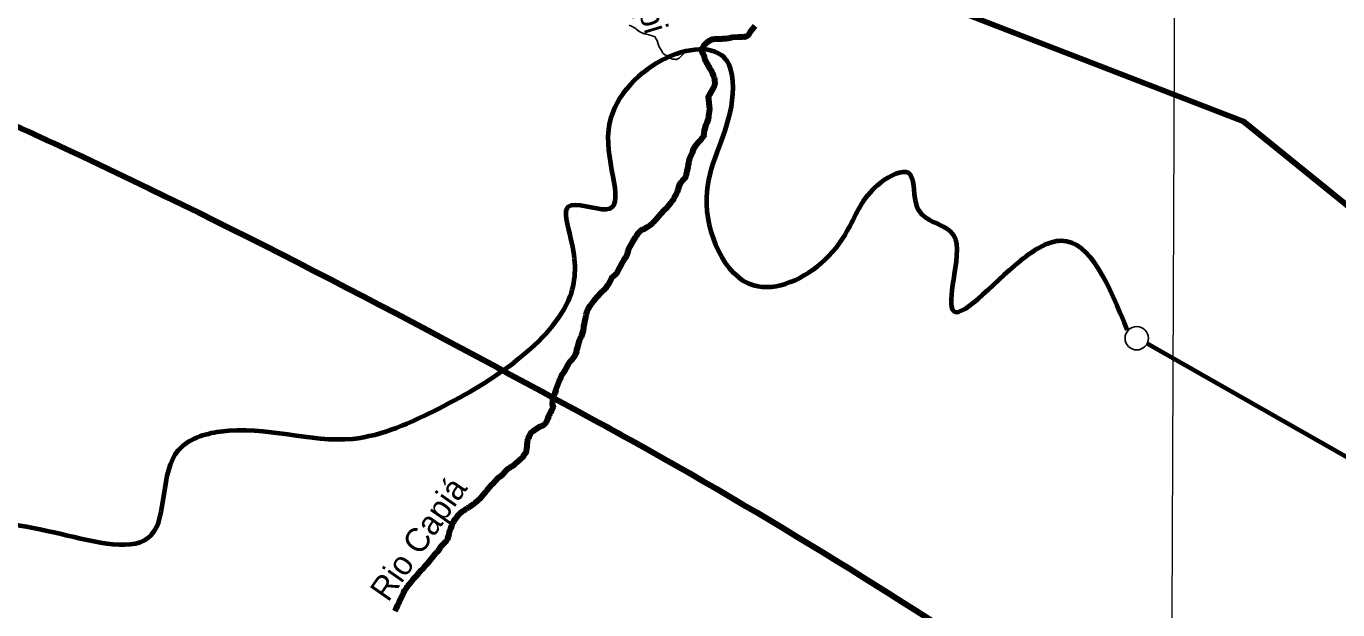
# Model space of a CAD drawing. Extents: x 553962 to 842807, y 8883888 to 9032388.
# Drawn here: x 640695 to 668185, y 8961392 to 8973626 of the extents above; entities that cross this region are included whole.
import ezdxf
from ezdxf.enums import TextEntityAlignment as Align

# ---------------------------------------------------------------- set-up
doc = ezdxf.new("R2010")
doc.units = 0
doc.header["$LTSCALE"] = 200
for name, color, linetype, lineweight in [('1', 7, 'Continuous', 13), ('24', 7, 'Continuous', 25), ('27', 7, 'Continuous', 25), ('51', 7, 'Continuous', 70), ('9', 7, 'Continuous', 90)]:
    doc.layers.add(name, color=color, linetype=linetype, lineweight=lineweight)
doc.layers.add('49', color=7, linetype='Continuous')

msp = doc.modelspace()

# ---------------------------------------------------------------- linework, layer by layer
at = {"layer": '1'}
msp.add_lwpolyline([(664968.2, 9023436.8), (664657.1, 8949509), (664397.1, 8890880.2)], dxfattribs=at)
at = {"layer": '24'}
for p, q in [((655116.6, 8973422.7), (655117, 8973424.3)), ((654851.3, 8973132), (654755.7, 8973142.7))]:
    msp.add_line(p, q, dxfattribs=at)
msp.add_lwpolyline([(654755.7, 8973142.7), (654720.6, 8973132.1), (654647.5, 8973144.9), (654604.9, 8973142), (654598.8, 8973140.5), (654534.6, 8973104.9), (654437.3, 8973012.6), (654419.5, 8972998.8), (654403.8, 8972979.2), (654381.6, 8972957.8), (654363, 8972946.1), (654335.2, 8972931.4), (654326.4, 8972929.3), (654308.8, 8972928.4), (654287.9, 8972933.5), (654250.2, 8972934.8), (654229.3, 8972940.7), (654192.4, 8972956.2), (654152.5, 8972986.8), (654147.8, 8972992.5), (654142.1, 8972995.3), (654139, 8973001.3), (654076, 8973035.9), (654041.5, 8973060), (654027.3, 8973074.1), (654028.3, 8973079.5), (653955, 8973206), (653948.8, 8973231.1), (653931.5, 8973279.1), (653918, 8973324.5), (653906.3, 8973348.1), (653892.5, 8973371.7), (653880.9, 8973398.6), (653873.4, 8973402.2), (653869.2, 8973406.6), (653838.8, 8973418.7), (653790.9, 8973428.7), (653697.5, 8973459.4), (653649.6, 8973468.4), (653604, 8973484.9), (653582.4, 8973495.6), (653556.1, 8973510.9), (653509.5, 8973541.4), (653482.9, 8973561.9), (653470.5, 8973577.6), (653442.6, 8973592.3), (653395.4, 8973620.1), (653335.2, 8973650.9)], dxfattribs=at)
at = {"layer": '24', "lineweight": 53}
for points in [[(655968.2, 8973630.5), (655940.3, 8973590.2), (655926.4, 8973572.3), (655907.2, 8973551.6), (655857.4, 8973488), (655825.2, 8973435), (655819.5, 8973432.4), (655817.1, 8973428.1), (655813, 8973426.4), (655807.3, 8973421.2), (655797.6, 8973417.6), (655794, 8973413), (655766.8, 8973403.9), (655745.4, 8973399.7), (655722.2, 8973400.4), (655702.5, 8973398.4), (655680.3, 8973394.3), (655616.9, 8973396.2), (655501.2, 8973386.6), (655443.3, 8973378), (655404.8, 8973367.5), (655366.2, 8973362.1), (655326.8, 8973361.9), (655289.1, 8973358.7), (655269, 8973355.7), (655249.7, 8973356.6), (655212, 8973355.5), (655191.9, 8973353.5), (655154.1, 8973354.5), (655137.5, 8973353.6), (655077.8, 8973346), (655060.3, 8973342.2), (655039.3, 8973335.4), (655029.9, 8973329.2), (655023.6, 8973328.5), (655016.9, 8973321.8), (654963.5, 8973284.3), (654916.4, 8973246.2), (654900.8, 8973228.3), (654881.6, 8973201), (654851.3, 8973132), (654852.3, 8973113.8), (654858.7, 8973088.2), (654878.1, 8973056.9), (654895, 8973014.3), (654909.2, 8972953.2), (654915.3, 8972934.7), (654923.6, 8972916.2), (654947.3, 8972875.3), (654982.1, 8972819.3), (654996.2, 8972794.1), (655005.3, 8972774), (655014.6, 8972757.2), (655044.4, 8972710.5), (655053.7, 8972692), (655056.5, 8972676.5), (655080.1, 8972632.6), (655093.2, 8972594.1), (655109.8, 8972556.3), (655111.9, 8972544), (655121.8, 8972516.9), (655124, 8972498.5), (655124.2, 8972478.4), (655127.3, 8972439.8), (655123.7, 8972391.1), (655118.2, 8972380.4), (655102.9, 8972341.9), (654992.2, 8972144.1), (655019.8, 8971884.2), (654998.6, 8971745.3), (654995, 8971695.3), (654989.7, 8971685.4), (654957.7, 8971597.4), (654937.6, 8971556.5), (654925.2, 8971519.5), (654918.6, 8971481), (654907, 8971442.4), (654896.1, 8971382.9), (654895.8, 8971344.4), (654892, 8971324.4), (654883.1, 8971306.7), (654872.7, 8971291.8), (654840.1, 8971251.1), (654818.4, 8971232.1), (654818.4, 8971232.1), (654777.1, 8971189.8), (654713.1, 8971114), (654675.8, 8971041.8), (654665.8, 8971017.4), (654650.1, 8970966.2), (654641.7, 8970946), (654616.5, 8970899.6)], [(654616.5, 8970899.6), (654597.8, 8970850.8), (654585.3, 8970804.5), (654581.2, 8970781.8), (654578.8, 8970758.3), (654572.6, 8970734.7), (654560.7, 8970664), (654554.4, 8970640.4), (654550, 8970616.9), (654542.2, 8970591.6), (654533, 8970547), (654526.8, 8970523.4), (654524.2, 8970501.2), (654508.2, 8970458.4), (654499, 8970437.8), (654493.5, 8970429), (654477.7, 8970417.1), (654443, 8970382.2), (654421.1, 8970358.3), (654389.5, 8970306.2), (654379.5, 8970284), (654365, 8970242.8), (654351.1, 8970197.8), (654345.4, 8970173.5), (654336.8, 8970149.9), (654324.7, 8970123.6), (654288, 8970056.4), (654272.8, 8970031.9), (654254.6, 8969979.6), (654230.2, 8969960.2), (654218.1, 8969945.2), (654200.3, 8969917.9), (654115.1, 8969812.6), (654066, 8969768.5), (653998.5, 8969693.6), (653949.1, 8969634.7), (653875.5, 8969551.6), (653848.1, 8969526.1), (653826.1, 8969509.2), (653807.7, 8969485.9), (653788.8, 8969465.8), (653781.7, 8969461.6), (653774.9, 8969453.3), (653733.8, 8969425.9), (653708.2, 8969413.9), (653656.8, 8969380.9), (653631.1, 8969367), (653605.4, 8969356.1), (653579.7, 8969340.1), (653534.3, 8969303.2), (653514.9, 8969279.7), (653477.3, 8969225.2), (653456.6, 8969199.3), (653405, 8969106.7), (653344.1, 8969008.1), (653319.5, 8968956.7), (653307.6, 8968905.3), (653300.6, 8968881.3), (653288.5, 8968853.8), (653281.5, 8968827.4), (653256.7, 8968776), (653222.5, 8968726.1), (653207.9, 8968699.7), (653188.9, 8968672.3), (653150.5, 8968597.6), (653133.3, 8968569.4), (653084.6, 8968470), (653068.7, 8968444.2), (653061.9, 8968437.6), (653060, 8968431.6), (653055, 8968429.5), (653045.5, 8968418.5), (652999.2, 8968380.5), (652979.1, 8968362.1), (652966, 8968345), (652949.9, 8968318.3), (652925.3, 8968271.2), (652905.8, 8968224.1), (652891.4, 8968201.3), (652870.7, 8968180.1), (652835.3, 8968129.2), (652814.8, 8968105.2), (652767.5, 8968061.3), (652745.1, 8968043.8), (652652.7, 8967947.3), (652575.9, 8967853), (652512.8, 8967770.6), (652464.1, 8967693.3), (652444.9, 8967645.2), (652429.5, 8967596.4), (652427.1, 8967572.9), (652423, 8967550.1), (652401.8, 8967461), (652386.5, 8967384.3), (652386.5, 8967384.3), (652384.2, 8967360.8), (652378.1, 8967337.2), (652377.6, 8967311.9), (652365.4, 8967244.7), (652334.5, 8967142.4), (652334.2, 8967141.5)], [(652334.2, 8967141.5), (652324.2, 8967104.9), (652322.5, 8967102.9), (652317.1, 8967102.6), (652315.6, 8967101.2), (652313.2, 8967092.4), (652305.8, 8967079.3), (652284.1, 8967031.6), (652276.2, 8967009.5), (652248.5, 8966903.2), (652229.6, 8966839.8), (652226.8, 8966816.7), (652221.7, 8966796.1), (652207.8, 8966753.2), (652174.8, 8966688.9), (652160.4, 8966666.8), (652125.1, 8966623.9), (652084.5, 8966580), (652063.4, 8966553.7), (652047.7, 8966528.9), (652014.7, 8966461.6), (651981.7, 8966407.3), (651960.2, 8966375.4), (651944.1, 8966347.6), (651912.1, 8966302.5), (651898.2, 8966276.2), (651897.4, 8966264.9), (651885.1, 8966236.2), (651874.7, 8966216.8), (651867.7, 8966193.9), (651851, 8966156.5), (651798.1, 8966019.3), (651792.6, 8965994.6), (651772.9, 8965932.8), (651759.8, 8965907.9), (651741.4, 8965863.8), (651729.4, 8965826.5), (651723.3, 8965779.3), (651720.3, 8965699.1), (651722.8, 8965675), (651743.5, 8965648.6), (651743.4, 8965644.6), (651698.9, 8965564), (651693.6, 8965544.1), (651688.2, 8965540.4), (651686.5, 8965534.9), (651674.3, 8965514.2), (651664.3, 8965494.4), (651655.9, 8965471.5), (651645.4, 8965450), (651637.1, 8965429.3), (651623.4, 8965385), (651601.4, 8965342.9), (651591.7, 8965321.5), (651577.2, 8965299.5), (651559.6, 8965280.8), (651533.4, 8965257.4), (651515.3, 8965247.1), (651499.6, 8965244.2), (651496.3, 8965241.1), (651479.6, 8965235.3), (651466.6, 8965226.9), (651443.2, 8965217.1), (651307.6, 8965130.1), (651287.6, 8965112.6), (651272.7, 8965096.7), (651258.7, 8965075.1), (651231.1, 8965023.9), (651213.3, 8964982.5), (651203.9, 8964956.5), (651195.2, 8964907.3), (651191.2, 8964841.6), (651191, 8964817.2), (651164.9, 8964678.6), (651157.3, 8964676.2), (651155.4, 8964668.4), (651148.9, 8964664.2), (651138.2, 8964651.3), (651124.9, 8964632.4), (651105.4, 8964599.6), (651094.6, 8964583.9), (651089.5, 8964580.2), (651065.3, 8964555.2), (651012.9, 8964509), (650998.5, 8964498.8), (650986.4, 8964486.1), (650949.3, 8964456), (650900.6, 8964412.3), (650874.5, 8964393.6), (650844.8, 8964377.2), (650826.4, 8964368.8), (650809.3, 8964357.4), (650785.7, 8964337.7), (650747.8, 8964302.8), (650693.7, 8964240.3), (650662, 8964208.7), (650662, 8964208.7), (650632.1, 8964188.2), (650618, 8964175.7), (650604.2, 8964169.9), (650589.6, 8964160.3)], [(650589.6, 8964160.3), (650574.3, 8964146.5), (650530.2, 8964098.3), (650509, 8964077.9), (650473.5, 8964033), (650442.6, 8964005.1), (650368.1, 8963919.8), (650346, 8963888.5), (650332.8, 8963874.9), (650310.5, 8963845.9), (650278.5, 8963808.1), (650264.2, 8963793.4), (650207.7, 8963725.5), (650176.4, 8963697.3), (650153.9, 8963678.9), (650140.4, 8963665.7), (650124.7, 8963653.2), (650103.3, 8963631.9), (650086.5, 8963618), (650072.4, 8963608.2), (650060.6, 8963597.7), (650046.6, 8963590.1), (650000.4, 8963555.6), (649955.2, 8963530.6), (649939, 8963520), (649922.4, 8963511.9), (649893.1, 8963492), (649865.1, 8963469.6), (649835.2, 8963451.3), (649777.6, 8963401.4), (649742.6, 8963367.3), (649718.9, 8963335.7), (649704, 8963312.6), (649674.6, 8963276.8), (649661.2, 8963257.8), (649648.9, 8963237.2), (649640.8, 8963219.3), (649630.7, 8963202.8), (649615, 8963169.3), (649608.8, 8963150.8), (649584.8, 8963092.3), (649563.2, 8963031.5), (649555.5, 8962980.1), (649545.2, 8962946.6), (649541.4, 8962928), (649515.6, 8962859.5), (649507.1, 8962843.2), (649499.9, 8962833.4), (649481.2, 8962814.6), (649475.3, 8962806.6), (649456.2, 8962788.3), (649449.4, 8962778.8), (649420.2, 8962753.5), (649395, 8962724.1), (649367.2, 8962685.5), (649343.5, 8962648.1), (649319.4, 8962615.6), (649289.5, 8962584.5), (649264.9, 8962562.7), (649217.7, 8962504.2), (649187.2, 8962469.5), (649162, 8962433.2), (649131.5, 8962399.3), (649105.7, 8962365.4), (649075.9, 8962335.3), (649056.5, 8962311.9), (649027.9, 8962268.9), (649013.5, 8962252.7), (648961.3, 8962205.6), (648876.1, 8962105.7), (648858.3, 8962087.9), (648839.2, 8962071.7), (648801.6, 8962026.5), (648742.1, 8961950.5), (648715.9, 8961919), (648698.4, 8961903), (648678.4, 8961875.1), (648665.1, 8961852.7), (648623.9, 8961794), (648612.1, 8961775.1), (648600.3, 8961752.7), (648585.9, 8961717.7), (648566.1, 8961679.4), (648547.4, 8961632), (648528.6, 8961598.4), (648520.4, 8961575.2), (648506.1, 8961547), (648501.5, 8961529.9), (648482.2, 8961497.1), (648474.8, 8961478.5), (648456.4, 8961445.7), (648449.2, 8961427.1), (648419.2, 8961360.9)]]:
    msp.add_lwpolyline(points, dxfattribs=at)
at = {"layer": '24'}
msp.add_spline([(665209.5, 8949437.1), (665261.8, 8949907.3), (665888.8, 8950560.5), (666750.9, 8951187.5), (667665.3, 8951814.5), (668344.5, 8952363.1), (668788.7, 8952911.7), (669180.6, 8953564.9), (669154.4, 8954270.2), (669755.3, 8954662.1), (670486.8, 8955027.9), (671218.3, 8955785.5), (671166.1, 8956360.3), (671531.8, 8956726), (671479.6, 8956987.3), (670957.1, 8957405.3), (670695.8, 8957849.4), (671139.9, 8958502.5), (671845.3, 8959207.9), (672394, 8958789.9), (673047.1, 8959234), (673465.1, 8959834.9), (673177.7, 8960461.9), (673987.6, 8960749.3), (675163.2, 8960879.9), (676103.7, 8960906.1), (677253.2, 8961428.6), (677697.4, 8961559.2), (678115.4, 8962133.9), (678611.8, 8962369.1), (678820.8, 8962919.9), (679291, 8963704.1), (679918, 8964226.8), (679944.1, 8964697.3), (679709, 8965272.3), (679291, 8966004.2), (678115.4, 8966945.2)], degree=3, dxfattribs=at)
at = {"layer": '27'}
msp.add_circle((663971.4, 8967084.9), 244.7, dxfattribs=at)
at = {"layer": '51'}
msp.add_line((664185.1, 8966978.4), (668643.6, 8964441.9), dxfattribs=at)
msp.add_spline([(592045.3, 8966365.8), (592105.7, 8965948), (594116, 8966514), (595498, 8965319.1), (597037.2, 8966136.7), (597979.5, 8965382), (598692.6, 8967300.2), (598221.4, 8968337.9), (598818.2, 8968400.8), (599792, 8969092.6), (600231.7, 8968589.5), (601299.7, 8967960.6), (602901.6, 8966545.5), (604566.4, 8966482.6), (604745.5, 8965696.5), (605405.1, 8964973.2), (606347.4, 8965067.5), (606598.7, 8965916.6), (607760.9, 8966168.1), (606881.4, 8967363.1), (606818.6, 8968966.8), (608671.8, 8969249.8), (610641.3, 8969878.8), (611740.7, 8970224.7), (613019.2, 8969721.5), (613813.8, 8969815.9), (614966.7, 8967143), (615657.7, 8967897.7), (616819.9, 8967551.8), (618578.9, 8965130.4), (619826, 8965948), (620642.7, 8965633.6), (621804.8, 8965948), (623218.3, 8965539.2), (624506.2, 8966105.2), (626233.7, 8967551.8), (628149.5, 8965483.5), (628181, 8964376.2), (628353.9, 8962908.5), (629301.3, 8963064.1), (629808.6, 8963286.1), (631079.5, 8963482.7), (632397.9, 8963531.7), (633735.2, 8964126.9), (635403.4, 8963798.6), (639270.5, 8963331.4), (641424.7, 8962981.9), (643321.9, 8962962.5), (643886.9, 8964740.5), (644763.1, 8965131.4), (647540.5, 8964979.2), (649340.2, 8965613.4), (651021.3, 8966658.1), (652098.8, 8967969.1), (652112.8, 8969176.8), (652061.5, 8969848.1), (652848.6, 8969790.3), (652905.5, 8971456.6), (655366.6, 8972918.5), (655467.9, 8971938.7), (654952.1, 8970029.5), (655937.5, 8968195.9), (657437.3, 8968728.9), (657964, 8969442.1), (658605, 8970350.9), (659181.8, 8970558.1), (659395.9, 8969769.5), (660070.2, 8969323), (660146.3, 8968426.2), (660105.6, 8967692), (661532.3, 8968708.4), (662385.2, 8969131.8), (663773.8, 8967258.4)], degree=3, dxfattribs=at)
at = {"layer": '9'}
for points in [[(657923.9, 8974844.3), (666205.7, 8971636.3), (671933.6, 8966993.4), (675245, 8966459.9), (693230.3, 8967549.5), (697027.9, 8970867.6)], [(655968.2, 8973630.5), (655940.3, 8973590.2), (655926.4, 8973572.3), (655907.2, 8973551.6), (655857.4, 8973488), (655825.2, 8973435), (655819.5, 8973432.4), (655817.1, 8973428.1), (655813, 8973426.4), (655807.3, 8973421.2), (655797.6, 8973417.6), (655794, 8973413), (655766.8, 8973403.9), (655745.4, 8973399.7), (655722.2, 8973400.4), (655702.5, 8973398.4), (655680.3, 8973394.3), (655616.9, 8973396.2), (655501.2, 8973386.6), (655443.3, 8973378), (655404.8, 8973367.5), (655366.2, 8973362.1), (655326.8, 8973361.9), (655289.1, 8973358.7), (655269, 8973355.7), (655249.7, 8973356.6), (655212, 8973355.5), (655191.9, 8973353.5), (655154.1, 8973354.5), (655137.5, 8973353.6), (655077.8, 8973346), (655060.3, 8973342.2), (655039.3, 8973335.4), (655029.9, 8973329.2), (655023.6, 8973328.5), (655016.9, 8973321.8), (654963.5, 8973284.3), (654916.4, 8973246.2), (654900.8, 8973228.3), (654881.6, 8973201), (654851.3, 8973132), (654852.3, 8973113.8), (654858.7, 8973088.2), (654878.1, 8973056.9), (654895, 8973014.3), (654909.2, 8972953.2), (654915.3, 8972934.7), (654923.6, 8972916.2), (654947.3, 8972875.3), (654982.1, 8972819.3), (654996.2, 8972794.1), (655005.3, 8972774), (655014.6, 8972757.2), (655044.4, 8972710.5), (655053.7, 8972692), (655056.5, 8972676.5), (655080.1, 8972632.6), (655093.2, 8972594.1), (655109.8, 8972556.3), (655111.9, 8972544), (655121.8, 8972516.9), (655124, 8972498.5), (655124.2, 8972478.4), (655127.3, 8972439.8), (655123.7, 8972391.1), (655118.2, 8972380.4), (655102.9, 8972341.9), (654992.2, 8972144.1), (655019.8, 8971884.2), (654998.6, 8971745.3), (654995, 8971695.3), (654989.7, 8971685.4), (654957.7, 8971597.4), (654937.6, 8971556.5), (654925.2, 8971519.5), (654918.6, 8971481), (654907, 8971442.4), (654896.1, 8971382.9), (654895.8, 8971344.4), (654892, 8971324.4), (654883.1, 8971306.7), (654872.7, 8971291.8), (654840.1, 8971251.1), (654818.4, 8971232.1), (654818.4, 8971232.1), (654777.1, 8971189.8), (654713.1, 8971114), (654675.8, 8971041.8), (654665.8, 8971017.4), (654650.1, 8970966.2), (654641.7, 8970946), (654616.5, 8970899.6)], [(654616.5, 8970899.6), (654597.8, 8970850.8), (654585.3, 8970804.5), (654581.2, 8970781.8), (654578.8, 8970758.3), (654572.6, 8970734.7), (654560.7, 8970664), (654554.4, 8970640.4), (654550, 8970616.9), (654542.2, 8970591.6), (654533, 8970547), (654526.8, 8970523.4), (654524.2, 8970501.2), (654508.2, 8970458.4), (654499, 8970437.8), (654493.5, 8970429), (654477.7, 8970417.1), (654443, 8970382.2), (654421.1, 8970358.3), (654389.5, 8970306.2), (654379.5, 8970284), (654365, 8970242.8), (654351.1, 8970197.8), (654345.4, 8970173.5), (654336.8, 8970149.9), (654324.7, 8970123.6), (654288, 8970056.4), (654272.8, 8970031.9), (654254.6, 8969979.6), (654230.2, 8969960.2), (654218.1, 8969945.2), (654200.3, 8969917.9), (654115.1, 8969812.6), (654066, 8969768.5), (653998.5, 8969693.6), (653949.1, 8969634.7), (653875.5, 8969551.6), (653848.1, 8969526.1), (653826.1, 8969509.2), (653807.7, 8969485.9), (653788.8, 8969465.8), (653781.7, 8969461.6), (653774.9, 8969453.3), (653733.8, 8969425.9), (653708.2, 8969413.9), (653656.8, 8969380.9), (653631.1, 8969367), (653605.4, 8969356.1), (653579.7, 8969340.1), (653534.3, 8969303.2), (653514.9, 8969279.7), (653477.3, 8969225.2), (653456.6, 8969199.3), (653405, 8969106.7), (653344.1, 8969008.1), (653319.5, 8968956.7), (653307.6, 8968905.3), (653300.6, 8968881.3), (653288.5, 8968853.8), (653281.5, 8968827.4), (653256.7, 8968776), (653222.5, 8968726.1), (653207.9, 8968699.7), (653188.9, 8968672.3), (653150.5, 8968597.6), (653133.3, 8968569.4), (653084.6, 8968470), (653068.7, 8968444.2), (653061.9, 8968437.6), (653060, 8968431.6), (653055, 8968429.5), (653045.5, 8968418.5), (652999.2, 8968380.5), (652979.1, 8968362.1), (652966, 8968345), (652949.9, 8968318.3), (652925.3, 8968271.2), (652905.8, 8968224.1), (652891.4, 8968201.3), (652870.7, 8968180.1), (652835.3, 8968129.2), (652814.8, 8968105.2), (652767.5, 8968061.3), (652745.1, 8968043.8), (652652.7, 8967947.3), (652575.9, 8967853), (652512.8, 8967770.6), (652464.1, 8967693.3), (652444.9, 8967645.2), (652429.5, 8967596.4), (652427.1, 8967572.9), (652423, 8967550.1), (652401.8, 8967461), (652386.5, 8967384.3), (652386.5, 8967384.3), (652384.2, 8967360.8), (652378.1, 8967337.2), (652377.6, 8967311.9), (652365.4, 8967244.7), (652334.5, 8967142.4), (652334.2, 8967141.5)], [(652334.2, 8967141.5), (652324.2, 8967104.9), (652322.5, 8967102.9), (652317.1, 8967102.6), (652315.6, 8967101.2), (652313.2, 8967092.4), (652305.8, 8967079.3), (652284.1, 8967031.6), (652276.2, 8967009.5), (652248.5, 8966903.2), (652229.6, 8966839.8), (652226.8, 8966816.7), (652221.7, 8966796.1), (652207.8, 8966753.2), (652174.8, 8966688.9), (652160.4, 8966666.8), (652125.1, 8966623.9), (652084.5, 8966580), (652063.4, 8966553.7), (652047.7, 8966528.9), (652014.7, 8966461.6), (651981.7, 8966407.3), (651960.2, 8966375.4), (651944.1, 8966347.6), (651912.1, 8966302.5), (651898.2, 8966276.2), (651897.4, 8966264.9), (651885.1, 8966236.2), (651874.7, 8966216.8), (651867.7, 8966193.9), (651851, 8966156.5), (651798.1, 8966019.3), (651792.6, 8965994.6), (651772.9, 8965932.8), (651759.8, 8965907.9), (651741.4, 8965863.8), (651729.4, 8965826.5), (651723.3, 8965779.3), (651720.3, 8965699.1), (651722.8, 8965675), (651743.5, 8965648.6), (651743.4, 8965644.6), (651698.9, 8965564), (651693.6, 8965544.1), (651688.2, 8965540.4), (651686.5, 8965534.9), (651674.3, 8965514.2), (651664.3, 8965494.4), (651655.9, 8965471.5), (651645.4, 8965450), (651637.1, 8965429.3), (651623.4, 8965385), (651601.4, 8965342.9), (651591.7, 8965321.5), (651577.2, 8965299.5), (651559.6, 8965280.8), (651533.4, 8965257.4), (651515.3, 8965247.1), (651499.6, 8965244.2), (651496.3, 8965241.1), (651479.6, 8965235.3), (651466.6, 8965226.9), (651443.2, 8965217.1), (651307.6, 8965130.1), (651287.6, 8965112.6), (651272.7, 8965096.7), (651258.7, 8965075.1), (651231.1, 8965023.9), (651213.3, 8964982.5), (651203.9, 8964956.5), (651195.2, 8964907.3), (651191.2, 8964841.6), (651191, 8964817.2), (651164.9, 8964678.6), (651157.3, 8964676.2), (651155.4, 8964668.4), (651148.9, 8964664.2), (651138.2, 8964651.3), (651124.9, 8964632.4), (651105.4, 8964599.6), (651094.6, 8964583.9), (651089.5, 8964580.2), (651065.3, 8964555.2), (651012.9, 8964509), (650998.5, 8964498.8), (650986.4, 8964486.1), (650949.3, 8964456), (650900.6, 8964412.3), (650874.5, 8964393.6), (650844.8, 8964377.2), (650826.4, 8964368.8), (650809.3, 8964357.4), (650785.7, 8964337.7), (650747.8, 8964302.8), (650693.7, 8964240.3), (650662, 8964208.7), (650662, 8964208.7), (650632.1, 8964188.2), (650618, 8964175.7), (650604.2, 8964169.9), (650589.6, 8964160.3)], [(650589.6, 8964160.3), (650574.3, 8964146.5), (650530.2, 8964098.3), (650509, 8964077.9), (650473.5, 8964033), (650442.6, 8964005.1), (650368.1, 8963919.8), (650346, 8963888.5), (650332.8, 8963874.9), (650310.5, 8963845.9), (650278.5, 8963808.1), (650264.2, 8963793.4), (650207.7, 8963725.5), (650176.4, 8963697.3), (650153.9, 8963678.9), (650140.4, 8963665.7), (650124.7, 8963653.2), (650103.3, 8963631.9), (650086.5, 8963618), (650072.4, 8963608.2), (650060.6, 8963597.7), (650046.6, 8963590.1), (650000.4, 8963555.6), (649955.2, 8963530.6), (649939, 8963520), (649922.4, 8963511.9), (649893.1, 8963492), (649865.1, 8963469.6), (649835.2, 8963451.3), (649777.6, 8963401.4), (649742.6, 8963367.3), (649718.9, 8963335.7), (649704, 8963312.6), (649674.6, 8963276.8), (649661.2, 8963257.8), (649648.9, 8963237.2), (649640.8, 8963219.3), (649630.7, 8963202.8), (649615, 8963169.3), (649608.8, 8963150.8), (649584.8, 8963092.3), (649563.2, 8963031.5), (649555.5, 8962980.1), (649545.2, 8962946.6), (649541.4, 8962928), (649515.6, 8962859.5), (649507.1, 8962843.2), (649499.9, 8962833.4), (649481.2, 8962814.6), (649475.3, 8962806.6), (649456.2, 8962788.3), (649449.4, 8962778.8), (649420.2, 8962753.5), (649395, 8962724.1), (649367.2, 8962685.5), (649343.5, 8962648.1), (649319.4, 8962615.6), (649289.5, 8962584.5), (649264.9, 8962562.7), (649217.7, 8962504.2), (649187.2, 8962469.5), (649162, 8962433.2), (649131.5, 8962399.3), (649105.7, 8962365.4), (649075.9, 8962335.3), (649056.5, 8962311.9), (649027.9, 8962268.9), (649013.5, 8962252.7), (648961.3, 8962205.6), (648876.1, 8962105.7), (648858.3, 8962087.9), (648839.2, 8962071.7), (648801.6, 8962026.5), (648742.1, 8961950.5), (648715.9, 8961919), (648698.4, 8961903), (648678.4, 8961875.1), (648665.1, 8961852.7), (648623.9, 8961794), (648612.1, 8961775.1), (648600.3, 8961752.7), (648585.9, 8961717.7), (648566.1, 8961679.4), (648547.4, 8961632), (648528.6, 8961598.4), (648520.4, 8961575.2), (648506.1, 8961547), (648501.5, 8961529.9), (648482.2, 8961497.1), (648474.8, 8961478.5), (648456.4, 8961445.7), (648449.2, 8961427.1), (648419.2, 8961360.9)]]:
    msp.add_lwpolyline(points, dxfattribs=at)
msp.add_spline([(637260.6, 8972975.8), (641524.5, 8971056.2), (652526.1, 8965412.7), (653164.3, 8965062.8), (670790.5, 8953770.1), (686194, 8943929.9), (696283.3, 8937647.1)], degree=3, dxfattribs=at)

# ---------------------------------------------------------------- texts
at = {"layer": '49'}
for s, rotation, p in [('Canapi', 286.879, (653368, 8974444.7)), ('Rio Capiá', 55.114, (649119.7, 8962738.4))]:
    msp.add_text(s, height=500, rotation=rotation, dxfattribs=at).set_placement(p, align=Align.CENTER)

doc.saveas('drawing.dxf')
